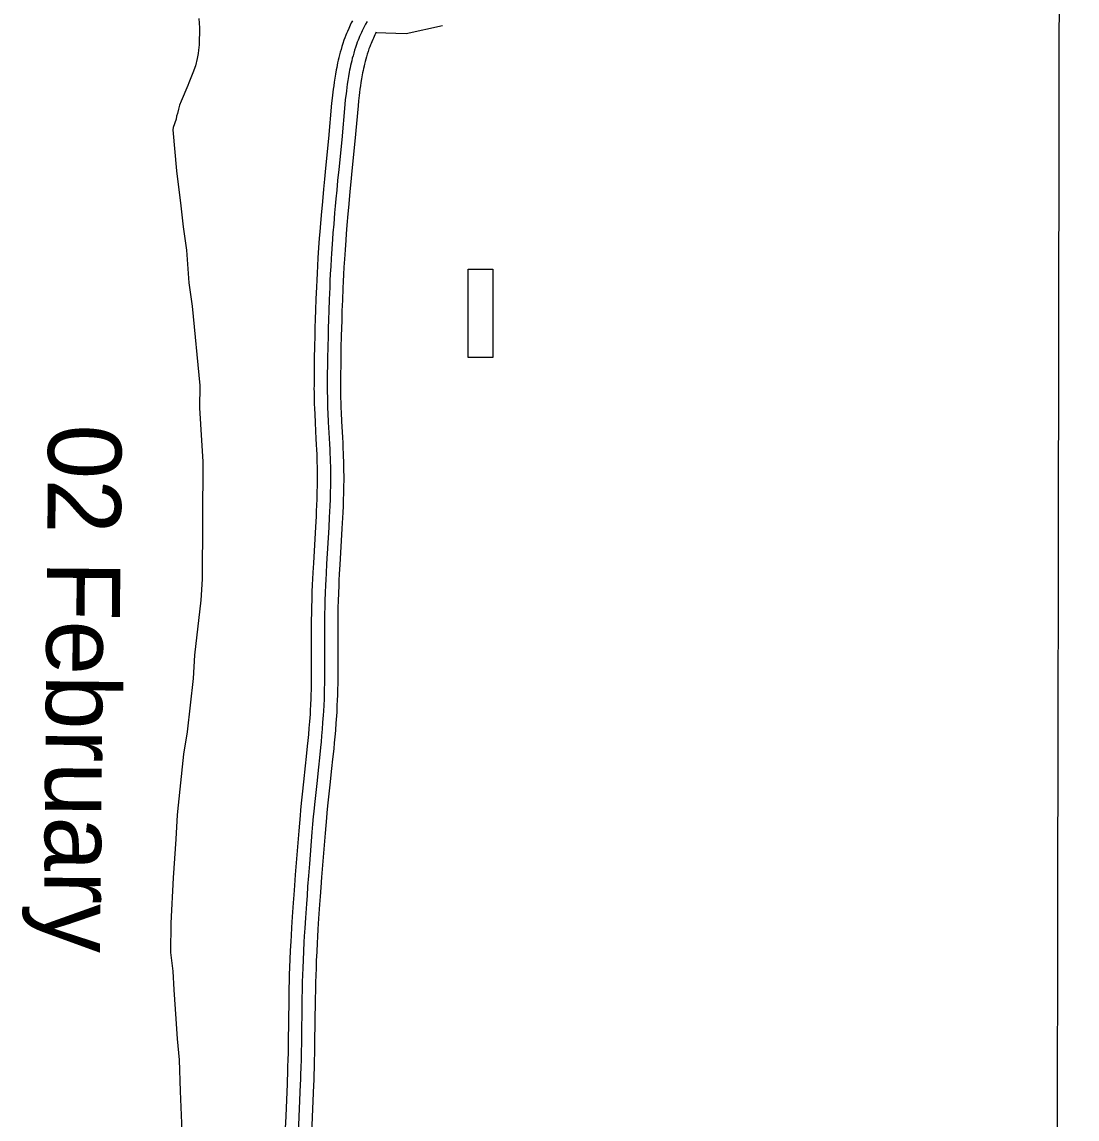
# Model space of a CAD drawing. Extents: x 3192952 to 3230831, y 849296 to 874698.
# Drawn here: x 3211675 to 3212870, y 861202 to 862444 of the extents above; entities that cross this region are included whole.
import ezdxf

# ---------------------------------------------------------------- set-up
doc = ezdxf.new("R2010")
doc.units = 0
for name, color, linetype in [('V-BLDG-OTLN', 7, 'Continuous'), ('V-GRID-MAJR', 7, 'Continuous'), ('V-RIVR-IDEN', 7, 'Continuous'), ('V-ROAD-CNTR', 7, 'Continuous'), ('V-SITE-VEGE', 7, 'Continuous'), ('V-TOPO-SHOR', 7, 'Continuous')]:
    doc.layers.add(name, color=color, linetype=linetype)

msp = doc.modelspace()

# ---------------------------------------------------------------- linework, layer by layer
at = {"layer": 'V-BLDG-OTLN'}
msp.add_lwpolyline([(3212208.8, 862164.3), (3212208.9, 862064.3), (3212180.9, 862064.3), (3212180.8, 862164.3)], close=True, dxfattribs=at)
at = {"layer": 'V-GRID-MAJR'}
msp.add_spline([(3212836, 854703.6), (3212847.5, 860762.7), (3212858.9, 866825.2), (3212870.4, 872887.8), (3212870.4, 872891.2)], degree=3, dxfattribs=at)
at = {"layer": 'V-ROAD-CNTR'}
for points in [[(3212049.8, 862445.9), (3212048.4, 862443.3), (3212047.3, 862441), (3212046.3, 862438.9), (3212045.5, 862437), (3212044, 862433.8), (3212043, 862431.4), (3212042.2, 862429.5), (3212041.2, 862426.6), (3212040.1, 862423.8), (3212038.9, 862420.2), (3212037.9, 862416.8), (3212036.9, 862413.4), (3212036, 862410.2), (3212035.1, 862407.1), (3212034.4, 862404.2)], [(3212066.3, 862444.9), (3212064.6, 862441.8), (3212063.1, 862439), (3212061.9, 862436.6), (3212060.8, 862434.4), (3212059.9, 862432.5), (3212059.1, 862430.9), (3212057.8, 862427.9), (3212056.9, 862425.7), (3212056.2, 862424), (3212055.2, 862421.4), (3212054.3, 862418.8), (3212053.2, 862415.6), (3212052.2, 862412.4), (3212051.3, 862409.3), (3212050.4, 862406.2), (3212049.6, 862403.3), (3212048.9, 862400.5)], [(3212076, 862432.6), (3212110.7, 862431.4), (3212151.9, 862440.4)], [(3212076.8, 862432.9), (3212076.4, 862432.1), (3212075.3, 862429.9), (3212074.3, 862427.9), (3212073.5, 862426.2), (3212072.8, 862424.7), (3212071.6, 862422), (3212070.8, 862420), (3212070.2, 862418.5), (3212069.3, 862416.2), (3212068.5, 862413.9), (3212067.5, 862410.9), (3212066.5, 862408), (3212065.7, 862405.1), (3212064.9, 862402.3), (3212064.2, 862399.6), (3212063.5, 862396.8)], [(3212034.3, 862404), (3212033.7, 862401.1), (3212033, 862398.3), (3212032.4, 862395.5), (3212031.9, 862392.9), (3212031.4, 862390.3), (3212030.5, 862385.3), (3212029.7, 862380.7), (3212029.1, 862376.3), (3212028.5, 862372.2), (3212028, 862368.4), (3212027.6, 862364.8), (3212026.8, 862358.2), (3212026.2, 862352.3), (3212022.6, 862312.4), (3212019.3, 862278.9), (3212018.1, 862266.3), (3212017, 862255.2), (3212016.1, 862245.6), (3212015.3, 862237.1), (3212014.6, 862229.7), (3212013.5, 862216.6), (3212012.7, 862206.9), (3212012.2, 862199.5), (3212011.4, 862188.5), (3212011.1, 862183), (3212010.7, 862177.4), (3212010.2, 862168.4), (3212009.8, 862159.9), (3212009.4, 862151.9), (3212009, 862144.5), (3212008.4, 862130.5), (3212007.9, 862118.2), (3212007.6, 862107.5), (3212007.3, 862098.2), (3212007.1, 862090), (3212006.8, 862075.6), (3212006.6, 862064.9), (3212006.5, 862056.8), (3212006.3, 862044.7), (3212006.3, 862032.6), (3212006.2, 862029), (3212006.3, 862025.4), (3212006.4, 862018.6), (3212006.5, 862012.3), (3212006.7, 862006.3), (3212007, 862000.7), (3212007.5, 861990.4), (3212008.4, 861972.4), (3212008.8, 861965.7), (3212009, 861959.9), (3212009.3, 861954.8), (3212009.4, 861950.3), (3212009.6, 861946.5), (3212009.8, 861939.7), (3212009.8, 861934.6), (3212009.9, 861930.9), (3212009.9, 861925.2), (3212009.8, 861919.6), (3212009.6, 861911.6), (3212009.4, 861904.1), (3212009.1, 861897), (3212008.8, 861890.4), (3212008.5, 861884.2), (3212007.9, 861872.5), (3212005.5, 861831.3), (3212005, 861821), (3212004.6, 861813.2), (3212004.3, 861807.3), (3212003.9, 861798.6), (3212003.6, 861789.7), (3212003.4, 861781.8), (3212003.3, 861774.3), (3212003.2, 861767.3), (3212003.2, 861760.8), (3212003.2, 861712.2), (3212003.2, 861706.2), (3212003.1, 861701), (3212003.1, 861696.4), (3212002.9, 861688.4), (3212002.7, 861682.4), (3212002.6, 861677.9), (3212002.3, 861671.2), (3212001.9, 861664.5), (3212001.7, 861660.4), (3212001.1, 861652.2), (3212000.5, 861644.5)], [(3212048.9, 862400.5), (3212048.3, 862397.7), (3212047.7, 862395.1), (3212047.1, 862392.5), (3212046.6, 862390), (3212046.1, 862387.5), (3212045.3, 862382.8), (3212044.5, 862378.3), (3212043.9, 862374.1), (3212043.4, 862370.2), (3212042.9, 862366.5), (3212042.5, 862363.1), (3212041.7, 862356.6), (3212041.1, 862350.9), (3212037.6, 862311), (3212034.2, 862277.4), (3212033, 862264.8), (3212031.9, 862253.8), (3212031, 862244.2), (3212030.2, 862235.7), (3212029.6, 862228.3), (3212028.5, 862215.4), (3212027.7, 862205.7), (3212027.1, 862198.4), (3212026.4, 862187.5), (3212026, 862182), (3212025.7, 862176.6), (3212025.2, 862167.5), (3212024.7, 862159.1), (3212024.3, 862151.2), (3212024, 862143.8), (3212023.4, 862129.9), (3212022.9, 862117.7), (3212022.6, 862107.1), (3212022.3, 862097.7), (3212022.1, 862089.6), (3212021.8, 862075.3), (3212021.6, 862064.6), (3212021.5, 862056.6), (3212021.3, 862044.6), (3212021.3, 862032.5), (3212021.2, 862029), (3212021.3, 862025.6), (3212021.4, 862018.9), (3212021.5, 862012.7), (3212021.7, 862006.9), (3212022, 862001.4), (3212022.4, 861991.1), (3212023.4, 861973.2), (3212023.7, 861966.4), (3212024, 861960.6), (3212024.3, 861955.4), (3212024.4, 861950.9), (3212024.6, 861946.9), (3212024.8, 861940), (3212024.8, 861934.9), (3212024.9, 861931), (3212024.9, 861925.1), (3212024.8, 861919.3), (3212024.6, 861911.2), (3212024.4, 861903.6), (3212024.1, 861896.4), (3212023.8, 861889.7), (3212023.5, 861883.4), (3212022.9, 861871.7), (3212020.5, 861830.5), (3212019.9, 861820.2), (3212019.6, 861812.5), (3212019.3, 861806.7), (3212018.9, 861798), (3212018.6, 861789.3), (3212018.4, 861781.4), (3212018.3, 861774.1), (3212018.2, 861767.2), (3212018.2, 861760.7), (3212018.2, 861712.2), (3212018.2, 861706.1), (3212018.1, 861700.8), (3212018.1, 861696.1), (3212017.9, 861688), (3212017.7, 861681.9), (3212017.6, 861677.3), (3212017.3, 861670.5), (3212016.9, 861663.6), (3212016.6, 861659.4), (3212016, 861651.1), (3212015.4, 861643.3)], [(3212063.5, 862397), (3212062.9, 862394.3), (3212062.3, 862391.8), (3212061.8, 862389.4), (3212061.3, 862387), (3212060.9, 862384.7), (3212060.1, 862380.2), (3212059.4, 862376), (3212058.7, 862372), (3212058.2, 862368.2), (3212057.8, 862364.7), (3212057.4, 862361.3), (3212056.6, 862355), (3212056.1, 862349.5), (3212052.5, 862309.6), (3212049.2, 862275.9), (3212047.9, 862263.4), (3212046.9, 862252.4), (3212045.9, 862242.8), (3212045.2, 862234.4), (3212044.5, 862227), (3212043.4, 862214.2), (3212042.7, 862204.5), (3212042.1, 862197.3), (3212041.4, 862186.5), (3212041, 862181.1), (3212040.7, 862175.7), (3212040.2, 862166.7), (3212039.7, 862158.3), (3212039.3, 862150.5), (3212039, 862143.1), (3212038.4, 862129.3), (3212037.9, 862117.2), (3212037.6, 862106.6), (3212037.3, 862097.3), (3212037.1, 862089.2), (3212036.8, 862075), (3212036.6, 862064.4), (3212036.5, 862056.4), (3212036.3, 862044.4), (3212036.3, 862032.5), (3212036.2, 862029), (3212036.3, 862025.7), (3212036.4, 862019.2), (3212036.5, 862013.2), (3212036.7, 862007.4), (3212036.9, 862002.1), (3212037.4, 861991.9), (3212038.4, 861974), (3212038.7, 861967.2), (3212039, 861961.3), (3212039.2, 861956), (3212039.4, 861951.4), (3212039.6, 861947.4), (3212039.8, 861940.4), (3212039.8, 861935.1), (3212039.9, 861931), (3212039.9, 861925), (3212039.8, 861919), (3212039.6, 861910.8), (3212039.4, 861903), (3212039.1, 861895.8), (3212038.8, 861889), (3212038.5, 861882.7), (3212037.9, 861870.8), (3212035.5, 861829.6), (3212034.9, 861819.4), (3212034.5, 861811.7), (3212034.3, 861806), (3212033.9, 861797.4), (3212033.6, 861788.8), (3212033.4, 861781.1), (3212033.3, 861773.9), (3212033.2, 861767.1), (3212033.2, 861760.7), (3212033.2, 861712.1), (3212033.2, 861706), (3212033.1, 861700.6), (3212033.1, 861695.9), (3212032.9, 861687.6), (3212032.7, 861681.4), (3212032.5, 861676.8), (3212032.2, 861669.8), (3212031.9, 861662.8), (3212031.6, 861658.4), (3212031, 861650), (3212030.4, 861642.1)], [(3212000.5, 861644.6), (3211999.9, 861637.3), (3211999.3, 861630.6), (3211998.6, 861624.3), (3211997.4, 861612.3), (3211996.3, 861601.9), (3211994.4, 861583.6), (3211992.9, 861569.8), (3211991.8, 861559.4), (3211991, 861551.6), (3211990.5, 861545.7), (3211989.7, 861536.9), (3211988.9, 861528.1), (3211986.1, 861491.9), (3211985, 861478.3), (3211984.1, 861466.3), (3211983.3, 861455.9), (3211982.6, 861446.8), (3211981.5, 861430.8), (3211980.8, 861418.7), (3211980.2, 861409.7), (3211979.9, 861402.9), (3211979.3, 861392.8), (3211978.8, 861382.6), (3211978.5, 861373.7), (3211978.2, 861365.3), (3211978, 861357.5), (3211977.8, 861350.2), (3211977.6, 861336.5), (3211977, 861289), (3211976.8, 861277.1), (3211976.6, 861268.3), (3211976.4, 861261.7), (3211976.1, 861251.7), (3211975.9, 861246.8), (3211975.7, 861241.8), (3211974.2, 861205), (3211973, 861177.4)], [(3212015.4, 861643.3), (3212014.8, 861636), (3212014.2, 861629.2), (3212013.6, 861622.8), (3212012.4, 861610.8), (3212011.3, 861600.3), (3212009.3, 861582), (3212007.8, 861568.2), (3212006.7, 861557.9), (3212006, 861550.2), (3212005.4, 861544.4), (3212004.6, 861535.6), (3212003.9, 861526.9), (3212001, 861490.7), (3212000, 861477.1), (3211999, 861465.2), (3211998.3, 861454.8), (3211997.6, 861445.7), (3211996.5, 861429.8), (3211995.7, 861417.8), (3211995.2, 861408.8), (3211994.8, 861402.1), (3211994.3, 861392), (3211993.8, 861381.9), (3211993.5, 861373.1), (3211993.2, 861364.9), (3211993, 861357.1), (3211992.8, 861349.9), (3211992.6, 861336.3), (3211991.9, 861288.7), (3211991.8, 861276.8), (3211991.6, 861267.9), (3211991.4, 861261.2), (3211991.1, 861251.2), (3211990.9, 861246.2), (3211990.7, 861241.2), (3211989.1, 861204.4), (3211987.9, 861176.8)], [(3212030.4, 861642), (3212029.8, 861634.7), (3212029.1, 861627.8), (3212028.5, 861621.3), (3212027.3, 861609.3), (3212026.2, 861598.7), (3212024.2, 861580.4), (3212022.7, 861566.7), (3212021.7, 861556.4), (3212020.9, 861548.7), (3212020.3, 861543), (3212019.6, 861534.3), (3212018.8, 861525.7), (3212016, 861489.5), (3212014.9, 861475.9), (3212014, 861464.1), (3212013.2, 861453.7), (3212012.6, 861444.6), (3212011.5, 861428.8), (3212010.7, 861416.9), (3212010.2, 861408), (3212009.8, 861401.3), (3212009.3, 861391.3), (3212008.8, 861381.3), (3212008.5, 861372.6), (3212008.2, 861364.4), (3212008, 861356.8), (3212007.8, 861349.6), (3212007.6, 861336.1), (3212006.9, 861288.5), (3212006.7, 861276.6), (3212006.6, 861267.6), (3212006.4, 861260.8), (3212006.1, 861250.7), (3212005.9, 861245.6), (3212005.7, 861240.6), (3212004.1, 861203.7), (3212002.9, 861176.1)]]:
    msp.add_lwpolyline(points, dxfattribs=at)
at = {"layer": 'V-SITE-VEGE'}
for p, q in [((3211875.8, 862448.5), (3211876.5, 862437.7)), ((3211876.5, 862437.7), (3211876, 862418.7)), ((3211875.6, 862412.6), (3211875.1, 862408.6)), ((3211876, 862418.7), (3211875.6, 862412.6)), ((3211874.1, 862402.9), (3211872.1, 862394.8)), ((3211875.1, 862408.6), (3211874.1, 862402.9)), ((3211869.1, 862386.9), (3211864.3, 862375.5)), ((3211872.1, 862394.8), (3211869.1, 862386.9)), ((3211864.3, 862375.5), (3211863.3, 862372.5)), ((3211863.3, 862372.5), (3211855.8, 862354.8)), ((3211854, 862350.1), (3211852.6, 862345.5)), ((3211855.8, 862354.8), (3211854, 862350.1)), ((3211850.6, 862337.7), (3211850, 862334.5)), ((3211851.6, 862340.6), (3211850.6, 862337.7)), ((3211852.6, 862345.5), (3211851.6, 862340.6)), ((3211846.8, 862324.8), (3211846.3, 862322.1)), ((3211850, 862334.5), (3211846.8, 862324.8)), ((3211846.3, 862322.1), (3211850.5, 862275.9)), ((3211850.5, 862275.9), (3211855.5, 862236.2)), ((3211855.5, 862236.2), (3211858, 862212.4)), ((3211858, 862212.4), (3211861.8, 862185.9)), ((3211861.8, 862185.9), (3211864.3, 862148.9)), ((3211864.3, 862148.9), (3211868.1, 862122.5)), ((3211868.1, 862122.5), (3211876.8, 862032.6)), ((3211876.8, 862032.6), (3211876.6, 862007.5)), ((3211876.6, 862007.5), (3211879, 861970.4)), ((3211879, 861970.4), (3211880.2, 861946.6)), ((3211880.2, 861946.6), (3211879.4, 861813.2)), ((3211879.4, 861813.2), (3211877.9, 861789.4)), ((3211877.9, 861789.4), (3211870.9, 861727.3)), ((3211870.9, 861727.3), (3211869.5, 861700.9)), ((3211869.5, 861700.9), (3211862.5, 861640.2)), ((3211862.5, 861640.2), (3211858.4, 861615.1)), ((3211858.4, 861615.1), (3211854.2, 861575.5)), ((3211854.2, 861575.5), (3211851.3, 861546.4)), ((3211851.3, 861546.4), (3211849.9, 861518.7)), ((3211849.9, 861518.7), (3211846.9, 861475.1)), ((3211846.9, 861475.1), (3211844, 861423.6)), ((3211844, 861423.6), (3211843.8, 861390.5)), ((3211843.8, 861390.5), (3211846.3, 861369.4)), ((3211846.3, 861369.4), (3211847.5, 861348.2)), ((3211847.5, 861348.2), (3211849.9, 861315.2)), ((3211849.9, 861315.2), (3211851.1, 861292.7)), ((3211851.1, 861292.7), (3211853.6, 861268.9)), ((3211853.6, 861268.9), (3211854.7, 861233.2)), ((3211854.7, 861233.2), (3211857, 861179))]:
    msp.add_line(p, q, dxfattribs=at)
at = {"layer": 'V-TOPO-SHOR'}
for points in [[(3211875.8, 862448.5), (3211876.5, 862437.7), (3211876, 862418.7), (3211875.6, 862412.6), (3211875.1, 862408.6), (3211874.1, 862402.9), (3211872.1, 862394.8), (3211869.1, 862386.9), (3211864.3, 862375.5), (3211863.3, 862372.5), (3211855.8, 862354.8), (3211854, 862350.1), (3211852.6, 862345.5), (3211851.6, 862340.6), (3211850.6, 862337.7), (3211850, 862334.5), (3211846.8, 862324.8), (3211846.3, 862322.1)], [(3211846.3, 862322.1), (3211850.5, 862275.9), (3211855.5, 862236.2), (3211858, 862212.4), (3211861.8, 862185.9), (3211864.3, 862148.9), (3211868.1, 862122.5), (3211876.8, 862032.6), (3211876.6, 862007.5), (3211879, 861970.4), (3211880.2, 861946.6), (3211879.4, 861813.2), (3211877.9, 861789.4), (3211870.9, 861727.3), (3211869.5, 861700.9), (3211862.5, 861640.2), (3211858.4, 861615.1), (3211854.2, 861575.5), (3211851.3, 861546.4), (3211849.9, 861518.7), (3211846.9, 861475.1), (3211844, 861423.6), (3211843.8, 861390.5), (3211846.3, 861369.4), (3211847.5, 861348.2), (3211849.9, 861315.2), (3211851.1, 861292.7), (3211853.6, 861268.9), (3211854.7, 861233.2), (3211857, 861179)]]:
    msp.add_lwpolyline(points, dxfattribs=at)

# ---------------------------------------------------------------- texts
at = {"layer": 'V-RIVR-IDEN'}
msp.add_text('02 February', height=83, rotation=269.5116, dxfattribs=at).set_placement((3211705.3, 861988.8))

doc.saveas('drawing.dxf')
